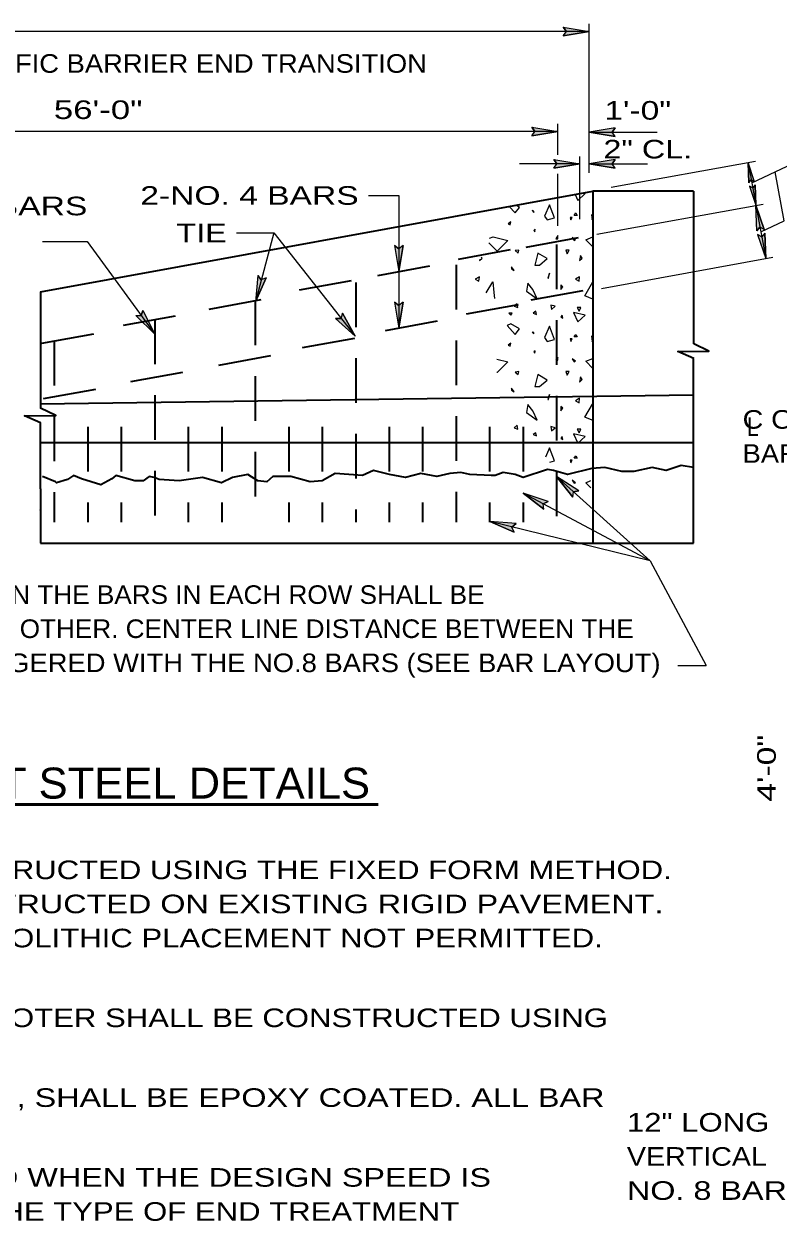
# Model space of a CAD drawing. Extents: x -11.7 to -4.5, y 8.6 to 18.8.
# Drawn here: x -8.704 to -6.272, y 11.081 to 14.943 of the extents above; entities that cross this region are included whole.
import ezdxf
from ezdxf.enums import TextEntityAlignment as Align

# ---------------------------------------------------------------- set-up
doc = ezdxf.new("R2010")
doc.units = 0
doc.header["$LTSCALE"] = 0.024
doc.linetypes.add('LONG_DASHED', pattern=[7.5, 6, -1.5])
for name, color, linetype, lineweight in [('1', 7, 'Continuous', 35), ('10', 7, 'Continuous', 13), ('12', 7, 'Continuous', 53), ('13', 7, 'Continuous', 53), ('6', 7, 'Continuous', 13)]:
    doc.layers.add(name, color=color, linetype=linetype, lineweight=lineweight)

msp = doc.modelspace()

# ---------------------------------------------------------------- hatches: boundary and pattern name
at = {"layer": '10'}
for points in [[(-6.8805, 14.919), (-6.9645, 14.905), (-6.954, 14.919), (-6.9645, 14.933)], [(-6.98233, 14.59633), (-7.06633, 14.58233), (-7.05583, 14.59633), (-7.06633, 14.61033)], [(-6.8805, 14.59433), (-6.7965, 14.58033), (-6.807, 14.59433), (-6.7965, 14.60833)], [(-6.91133, 14.49133), (-6.99533, 14.47733), (-6.98483, 14.49133), (-6.99533, 14.50533)], [(-6.8805, 14.49133), (-6.7965, 14.47733), (-6.807, 14.49133), (-6.7965, 14.50533)], [(-6.34717, 14.43383), (-6.36817, 14.4965), (-6.36583, 14.4305), (-6.358, 14.44017)], [(-6.34283, 14.35783), (-6.34533, 14.42367), (-6.35317, 14.414), (-6.364, 14.42017)], [(-6.34283, 14.35783), (-6.31667, 14.2795), (-6.33017, 14.2875), (-6.34017, 14.27533)], [(-6.3115, 14.186), (-6.31467, 14.2685), (-6.3245, 14.25617), (-6.338, 14.264)], [(-7.49467, 14.14417), (-7.48067, 14.22817), (-7.49467, 14.21767), (-7.50867, 14.22817)], [(-7.95733, 14.0465), (-7.92217, 14.12417), (-7.9385, 14.11767), (-7.94933, 14.13133)], [(-8.28217, 13.94267), (-8.343, 14.00233), (-8.3255, 14.00217), (-8.3205, 14.01883)], [(-7.49467, 13.96167), (-7.48067, 14.04567), (-7.49467, 14.03517), (-7.50867, 14.04567)], [(-7.636, 13.9355), (-7.67683, 14.01017), (-7.68133, 13.99317), (-7.699, 13.99283)], [(-6.98583, 13.483), (-6.93317, 13.416), (-6.9315, 13.4335), (-6.91417, 13.43683)], [(-7.09417, 13.42933), (-7.02667, 13.3775), (-7.02933, 13.39483), (-7.0135, 13.40217)], [(-7.2015, 13.33733), (-7.12317, 13.30383), (-7.13, 13.32), (-7.11667, 13.331)]]:
    msp.add_hatch(color=256, dxfattribs=at).paths.add_polyline_path(points)

# ---------------------------------------------------------------- linework, layer by layer
at = {"layer": '1'}
for p, q in [((-8.65083, 14.079), (-6.86867, 14.403)), ((-6.5445, 14.403), (-6.86867, 14.403)), ((-6.86867, 14.403), (-6.86867, 13.2685)), ((-7.08383, 14.223), (-6.91567, 14.25367)), ((-7.3025, 14.1845), (-7.1345, 14.21517)), ((-7.563, 14.1315), (-7.39483, 14.16217)), ((-7.81533, 14.085), (-7.64733, 14.1155)), ((-7.0685, 14.0525), (-6.9005, 14.083)), ((-8.10667, 14.02333), (-7.93867, 14.05383)), ((-7.27667, 14.0075), (-7.10867, 14.038)), ((-8.38283, 13.97117), (-8.21483, 14.00183)), ((-7.538, 13.95417), (-7.37, 13.98483)), ((-8.646, 13.91317), (-8.478, 13.94367)), ((-7.805, 13.89867), (-7.63683, 13.92917)), ((-8.07533, 13.84267), (-7.90717, 13.87317)), ((-8.35967, 13.789), (-8.1915, 13.81967)), ((-8.64067, 13.73417), (-8.4725, 13.76483)), ((-8.65167, 13.717), (-6.54483, 13.7465)), ((-8.65083, 13.59283), (-6.54483, 13.59283)), ((-8.65083, 13.2685), (-6.54483, 13.2685))]:
    msp.add_line(p, q, dxfattribs=at)
at = {"layer": '1', "linetype": 'LONG_DASHED'}
for p, q in [((-6.986, 14.23133), (-6.986, 13.33583)), ((-7.31, 14.16583), (-7.31, 13.33583)), ((-7.634, 14.109), (-7.634, 13.33583)), ((-7.958, 14.05033), (-7.958, 13.33583)), ((-8.28217, 13.9895), (-8.28217, 13.33583)), ((-8.60617, 13.92033), (-8.60617, 13.33583)), ((-8.49817, 13.64333), (-8.49817, 13.33583)), ((-8.39017, 13.64333), (-8.39017, 13.33583)), ((-8.17417, 13.64333), (-8.17417, 13.33583)), ((-8.06617, 13.64333), (-8.06617, 13.33583)), ((-7.85, 13.64333), (-7.85, 13.33583)), ((-7.742, 13.64333), (-7.742, 13.33583)), ((-7.526, 13.64333), (-7.526, 13.33583)), ((-7.418, 13.64333), (-7.418, 13.33583)), ((-7.202, 13.64333), (-7.202, 13.33583)), ((-7.094, 13.64333), (-7.094, 13.33583))]:
    msp.add_line(p, q, dxfattribs=at)
at = {"layer": '1'}
msp.add_lwpolyline([(-6.54483, 13.51167), (-6.58383, 13.51817), (-6.6325, 13.502), (-6.67783, 13.51167), (-6.73633, 13.49867), (-6.77533, 13.49867), (-6.8305, 13.51167), (-6.87267, 13.5085), (-6.9505, 13.489), (-6.996, 13.502), (-7.01533, 13.50517), (-7.09333, 13.47933), (-7.11917, 13.489), (-7.15817, 13.4955), (-7.18417, 13.48583), (-7.19717, 13.48583), (-7.26533, 13.489), (-7.2945, 13.4955), (-7.33017, 13.49233), (-7.37233, 13.4825), (-7.42433, 13.49233), (-7.473, 13.47933), (-7.52483, 13.489), (-7.57683, 13.502), (-7.6125, 13.48583), (-7.7, 13.49233), (-7.74233, 13.4695), (-7.78117, 13.46633), (-7.84283, 13.4825), (-7.90133, 13.4825), (-7.92083, 13.46633), (-7.95, 13.4695), (-7.98233, 13.489), (-8.03117, 13.47933), (-8.06683, 13.463), (-8.1285, 13.47933), (-8.203, 13.4695), (-8.268, 13.47283), (-8.28417, 13.47933), (-8.30033, 13.4825), (-8.31983, 13.4695), (-8.34583, 13.4695), (-8.4075, 13.48583), (-8.4205, 13.476), (-8.45617, 13.4565), (-8.51783, 13.476), (-8.54383, 13.48583), (-8.56333, 13.47283), (-8.599, 13.463), (-8.60217, 13.46633), (-8.64433, 13.4825)], dxfattribs=at)
at = {"layer": '10'}
for p, q in [((-6.8805, 14.919), (-9.01333, 14.919)), ((-6.9645, 14.933), (-6.8805, 14.919)), ((-6.9645, 14.933), (-6.954, 14.919)), ((-6.9645, 14.905), (-6.8805, 14.919)), ((-6.9645, 14.905), (-6.954, 14.919)), ((-6.8805, 14.463), (-6.8805, 14.943)), ((-7.06633, 14.61033), (-6.98233, 14.59633)), ((-7.06633, 14.61033), (-7.05583, 14.59633)), ((-6.98233, 14.52067), (-6.98233, 14.62033)), ((-6.7965, 14.60833), (-6.8805, 14.59433)), ((-6.7965, 14.60833), (-6.807, 14.59433)), ((-6.98233, 14.59633), (-8.962, 14.59633)), ((-7.06633, 14.58233), (-6.98233, 14.59633)), ((-7.06633, 14.58233), (-7.05583, 14.59633)), ((-6.8805, 14.59433), (-6.66117, 14.59433)), ((-6.7965, 14.58033), (-6.8805, 14.59433)), ((-6.7965, 14.58033), (-6.807, 14.59433)), ((-6.35617, 14.43083), (-6.13917, 14.5335)), ((-6.91133, 14.49133), (-7.10567, 14.49133)), ((-6.99533, 14.50533), (-6.91133, 14.49133)), ((-6.99533, 14.50533), (-6.98483, 14.49133)), ((-6.99533, 14.47733), (-6.91133, 14.49133)), ((-6.99533, 14.47733), (-6.98483, 14.49133)), ((-6.91133, 14.31367), (-6.91133, 14.51533)), ((-6.7965, 14.50533), (-6.8805, 14.49133)), ((-6.8805, 14.49133), (-6.69267, 14.49133)), ((-6.7965, 14.47733), (-6.8805, 14.49133)), ((-6.81, 14.41617), (-6.3445, 14.50083)), ((-6.7965, 14.50533), (-6.807, 14.49133)), ((-6.7965, 14.47733), (-6.807, 14.49133)), ((-6.36583, 14.4305), (-6.36817, 14.4965)), ((-6.34717, 14.43383), (-6.36817, 14.4965)), ((-6.98233, 14.2915), (-6.98233, 14.45967)), ((-6.36583, 14.4305), (-6.358, 14.44017)), ((-6.364, 14.42017), (-6.34283, 14.35783)), ((-6.364, 14.42017), (-6.35317, 14.414)), ((-6.34717, 14.43383), (-6.358, 14.44017)), ((-6.34533, 14.42367), (-6.35317, 14.414)), ((-6.34533, 14.42367), (-6.34283, 14.35783)), ((-7.59283, 14.38967), (-7.49467, 14.38967)), ((-6.85667, 14.26433), (-6.31933, 14.362)), ((-6.34017, 14.27533), (-6.34283, 14.35783)), ((-6.31667, 14.2795), (-6.34283, 14.35783)), ((-7.89833, 14.26883), (-7.95733, 14.0465)), ((-6.34017, 14.27533), (-6.33017, 14.2875)), ((-6.338, 14.264), (-6.3115, 14.186)), ((-6.338, 14.264), (-6.3245, 14.25617)), ((-6.31667, 14.2795), (-6.33017, 14.2875)), ((-6.31467, 14.2685), (-6.3245, 14.25617)), ((-6.31467, 14.2685), (-6.3115, 14.186)), ((-8.644, 14.24167), (-8.5005, 14.24167)), ((-8.5005, 14.24167), (-8.28217, 13.94267)), ((-7.50867, 14.22817), (-7.49467, 14.14417)), ((-7.50867, 14.22817), (-7.49467, 14.21767)), ((-7.48067, 14.22817), (-7.49467, 14.14417)), ((-7.48067, 14.22817), (-7.49467, 14.21767)), ((-6.84067, 14.08967), (-6.288, 14.19017)), ((-7.94933, 14.13133), (-7.95733, 14.0465)), ((-7.92217, 14.12417), (-7.95733, 14.0465)), ((-7.94933, 14.13133), (-7.9385, 14.11767)), ((-7.92217, 14.12417), (-7.9385, 14.11767)), ((-8.3205, 14.01883), (-8.3255, 14.00217)), ((-8.3205, 14.01883), (-8.28217, 13.94267)), ((-7.50867, 14.04567), (-7.49467, 13.96167)), ((-7.50867, 14.04567), (-7.49467, 14.03517)), ((-7.48067, 14.04567), (-7.49467, 13.96167)), ((-7.48067, 14.04567), (-7.49467, 14.03517)), ((-8.343, 14.00233), (-8.28217, 13.94267)), ((-8.343, 14.00233), (-8.3255, 14.00217)), ((-7.699, 13.99283), (-7.68133, 13.99317)), ((-7.699, 13.99283), (-7.636, 13.9355)), ((-7.67683, 14.01017), (-7.68133, 13.99317)), ((-7.67683, 14.01017), (-7.636, 13.9355)), ((-6.93317, 13.416), (-6.98583, 13.483)), ((-6.91417, 13.43683), (-6.98583, 13.483)), ((-6.68417, 13.21083), (-7.09417, 13.42933)), ((-7.02667, 13.3775), (-7.09417, 13.42933)), ((-7.0135, 13.40217), (-7.09417, 13.42933)), ((-7.0135, 13.40217), (-7.02933, 13.39483)), ((-6.93317, 13.416), (-6.9315, 13.4335)), ((-6.91417, 13.43683), (-6.9315, 13.4335)), ((-7.02667, 13.3775), (-7.02933, 13.39483)), ((-6.68417, 13.21083), (-7.2015, 13.33733)), ((-7.12317, 13.30383), (-7.2015, 13.33733)), ((-7.11667, 13.331), (-7.2015, 13.33733)), ((-7.11667, 13.331), (-7.13, 13.32)), ((-7.12317, 13.30383), (-7.13, 13.32)), ((-6.59517, 12.8735), (-6.504, 12.8735))]:
    msp.add_line(p, q, dxfattribs=at)
at = {"layer": '10', "lineweight": 35}
for p, q in [((-6.5445, 14.403), (-6.5445, 13.91083)), ((-8.65083, 14.079), (-8.65083, 13.70267)), ((-6.54483, 13.2685), (-6.54483, 13.86417)), ((-8.65083, 13.4435), (-8.65083, 13.65717)), ((-8.65083, 13.44283), (-8.65083, 13.2685)), ((-8.65083, 13.37467), (-8.65083, 13.37533))]:
    msp.add_line(p, q, dxfattribs=at)
at = {"layer": '10'}
for points in [[(-6.8805, 14.919), (-6.9645, 14.905), (-6.954, 14.919), (-6.9645, 14.933)], [(-6.98233, 14.59633), (-7.06633, 14.58233), (-7.05583, 14.59633), (-7.06633, 14.61033)], [(-6.8805, 14.59433), (-6.7965, 14.58033), (-6.807, 14.59433), (-6.7965, 14.60833)], [(-6.91133, 14.49133), (-6.99533, 14.47733), (-6.98483, 14.49133), (-6.99533, 14.50533)], [(-6.8805, 14.49133), (-6.7965, 14.47733), (-6.807, 14.49133), (-6.7965, 14.50533)], [(-6.34717, 14.43383), (-6.36817, 14.4965), (-6.36583, 14.4305), (-6.358, 14.44017)], [(-6.34283, 14.35783), (-6.34533, 14.42367), (-6.35317, 14.414), (-6.364, 14.42017)], [(-6.34283, 14.35783), (-6.31667, 14.2795), (-6.33017, 14.2875), (-6.34017, 14.27533)], [(-6.3115, 14.186), (-6.31467, 14.2685), (-6.3245, 14.25617), (-6.338, 14.264)], [(-7.49467, 14.14417), (-7.48067, 14.22817), (-7.49467, 14.21767), (-7.50867, 14.22817)], [(-7.95733, 14.0465), (-7.92217, 14.12417), (-7.9385, 14.11767), (-7.94933, 14.13133)], [(-8.28217, 13.94267), (-8.343, 14.00233), (-8.3255, 14.00217), (-8.3205, 14.01883)], [(-7.49467, 13.96167), (-7.48067, 14.04567), (-7.49467, 14.03517), (-7.50867, 14.04567)], [(-7.636, 13.9355), (-7.67683, 14.01017), (-7.68133, 13.99317), (-7.699, 13.99283)], [(-6.98583, 13.483), (-6.93317, 13.416), (-6.9315, 13.4335), (-6.91417, 13.43683)], [(-7.09417, 13.42933), (-7.02667, 13.3775), (-7.02933, 13.39483), (-7.0135, 13.40217)], [(-7.2015, 13.33733), (-7.12317, 13.30383), (-7.13, 13.32), (-7.11667, 13.331)]]:
    msp.add_lwpolyline(points, close=True, dxfattribs=at)
for points in [[(-6.36817, 14.4965), (-6.34283, 14.35783), (-6.3115, 14.186)], [(-6.32717, 14.27183), (-6.25233, 14.30733), (-6.28133, 14.46617)], [(-7.49467, 14.38967), (-7.49467, 14.14417), (-7.49467, 13.96367)], [(-8.01833, 14.26883), (-7.89833, 14.26883), (-7.636, 13.9355)], [(-6.98583, 13.483), (-6.68417, 13.21083), (-6.504, 12.8735)]]:
    msp.add_lwpolyline(points, dxfattribs=at)
at = {"layer": '10', "lineweight": 35}
for points in [[(-6.54367, 13.86417), (-6.59517, 13.88667), (-6.4945, 13.8875), (-6.54367, 13.91083)], [(-8.6505, 13.65633), (-8.702, 13.67883), (-8.60133, 13.67967), (-8.6505, 13.703)]]:
    msp.add_lwpolyline(points, dxfattribs=at)
at = {"layer": '12'}
msp.add_line((-9.947, 12.42533), (-7.561, 12.42533), dxfattribs=at)
at = {"layer": '6'}
for points in [[(-6.92633, 14.3925), (-6.91733, 14.37367), (-6.89333, 14.39567), (-6.9005, 14.39717)], [(-7.13867, 14.35383), (-7.1195, 14.33333), (-7.10517, 14.351), (-7.11683, 14.35783)], [(-6.86867, 14.32567), (-6.87317, 14.327), (-6.87083, 14.31067), (-6.86867, 14.31917)], [(-7.202, 14.2515), (-7.19, 14.2565), (-7.1435, 14.2445), (-7.178, 14.20983), (-7.205, 14.23683)], [(-6.86867, 14.2235), (-6.8915, 14.24633), (-6.86867, 14.25583)], [(-7.23417, 14.18317), (-7.23467, 14.17967), (-7.2265, 14.18783), (-7.22883, 14.191)], [(-7.213, 14.07533), (-7.192, 14.111), (-7.18817, 14.0765), (-7.18667, 14.057)], [(-6.86867, 14.05483), (-6.89533, 14.06633), (-6.86883, 14.111), (-6.86867, 14.10817)], [(-6.86867, 13.93383), (-6.87317, 13.93533), (-6.87083, 13.919), (-6.86867, 13.92733)], [(-7.17867, 13.86183), (-7.1435, 13.85267), (-7.178, 13.81817), (-7.17867, 13.81867)], [(-6.86867, 13.83183), (-6.8915, 13.85467), (-6.86867, 13.864)], [(-6.87167, 13.66433), (-6.89533, 13.67467), (-6.87067, 13.71617)], [(-7.00783, 13.5295), (-6.99233, 13.5335), (-7.00867, 13.57567), (-7.022, 13.54517)], [(-6.87567, 13.447), (-6.8915, 13.46283), (-6.87517, 13.46967)]]:
    msp.add_lwpolyline(points, dxfattribs=at)
for points in [[(-7.059, 14.339), (-7.06483, 14.341), (-7.059, 14.33517)], [(-7.01633, 14.31067), (-6.99233, 14.317), (-7.00867, 14.35917), (-7.0245, 14.32317)], [(-6.92367, 14.33333), (-6.91933, 14.32517), (-6.92933, 14.32517)], [(-7.14167, 14.29867), (-7.13583, 14.29483), (-7.1335, 14.305)], [(-6.94183, 14.31883), (-6.94, 14.31067), (-6.93567, 14.31883)], [(-7.05467, 14.2805), (-7.059, 14.27667), (-7.05667, 14.27233)], [(-6.98217, 14.26033), (-6.988, 14.25017), (-6.98217, 14.25017)], [(-6.92933, 14.2445), (-6.9255, 14.24633), (-6.93567, 14.2545)], [(-7.1195, 14.21183), (-7.1095, 14.20367), (-7.1075, 14.21367)], [(-6.95583, 14.21367), (-6.952, 14.20167), (-6.94567, 14.21367)], [(-7.04083, 14.16517), (-7.01633, 14.18583), (-7.0465, 14.20367), (-7.05667, 14.16517)], [(-6.90917, 14.196), (-6.91167, 14.17967), (-6.9035, 14.18783)], [(-7.1315, 14.1595), (-7.1315, 14.15317), (-7.12333, 14.1475)], [(-7.01433, 14.123), (-7.0125, 14.123), (-7.00867, 14.13933)], [(-7.24867, 14.11917), (-7.23667, 14.11283), (-7.23467, 14.12733)], [(-7.07917, 14.10667), (-7.083, 14.08067), (-7.049, 14.05633), (-7.06283, 14.0865)], [(-6.97217, 14.10083), (-6.97217, 14.0865), (-6.96583, 14.09467)], [(-6.9255, 14.11917), (-6.9135, 14.11283), (-6.91167, 14.12733)], [(-7.11333, 14.0405), (-7.12333, 14.03233), (-7.11133, 14.028)], [(-7.00433, 14.03617), (-7.00233, 14.02217), (-6.99033, 14.03233)], [(-6.91933, 14.028), (-6.9135, 14.016), (-6.90733, 14.028)], [(-7.13967, 14.01017), (-7.1335, 14.004), (-7.12967, 14.01017)], [(-7.061, 14.01017), (-7.05083, 14.00583), (-7.05283, 14.016)], [(-6.97217, 13.99767), (-6.96583, 13.99383), (-6.96783, 14.004)], [(-6.93183, 14.01217), (-6.91733, 13.98183), (-6.89333, 14.004)], [(-7.14583, 13.96983), (-7.1195, 13.9415), (-7.10517, 13.95933), (-7.1335, 13.97567)], [(-7.059, 13.94733), (-7.06483, 13.94917), (-7.059, 13.9435)], [(-7.01633, 13.919), (-6.99233, 13.92517), (-7.00867, 13.9675), (-7.0245, 13.9315)], [(-7.14167, 13.907), (-7.13583, 13.90317), (-7.1335, 13.91317)], [(-6.94183, 13.92717), (-6.94, 13.919), (-6.93567, 13.92717)], [(-6.92367, 13.9415), (-6.91933, 13.93333), (-6.92933, 13.93333)], [(-7.05467, 13.88867), (-7.059, 13.88483), (-7.05667, 13.8805)], [(-6.98217, 13.8685), (-6.988, 13.8585), (-6.98217, 13.8585)], [(-6.92933, 13.85267), (-6.9255, 13.85467), (-6.93567, 13.86283)], [(-7.1195, 13.82), (-7.1095, 13.81183), (-7.1075, 13.822)], [(-7.04083, 13.7735), (-7.01633, 13.79417), (-7.0465, 13.81183), (-7.05667, 13.7735)], [(-6.95583, 13.822), (-6.952, 13.81), (-6.94567, 13.822)], [(-6.90917, 13.80417), (-6.91167, 13.78783), (-6.9035, 13.796)], [(-7.1315, 13.76767), (-7.1315, 13.7615), (-7.12333, 13.75567)], [(-7.07917, 13.715), (-7.083, 13.689), (-7.049, 13.6645), (-7.06283, 13.69483)], [(-7.01433, 13.73133), (-7.0125, 13.73133), (-7.00867, 13.7475)], [(-6.9255, 13.72733), (-6.9135, 13.72117), (-6.91167, 13.7355)], [(-6.97217, 13.70917), (-6.97217, 13.69483), (-6.96583, 13.703)], [(-7.11333, 13.64867), (-7.12333, 13.6405), (-7.11133, 13.63617)], [(-7.00433, 13.64433), (-7.00233, 13.6305), (-6.99033, 13.6405)], [(-6.91933, 13.63617), (-6.9135, 13.62417), (-6.90733, 13.63617)], [(-7.061, 13.6185), (-7.05083, 13.61417), (-7.05283, 13.62417)], [(-6.97217, 13.606), (-6.96583, 13.60217), (-6.96783, 13.61217)], [(-6.93183, 13.62033), (-6.91733, 13.59017), (-6.89333, 13.61217)], [(-6.94183, 13.53533), (-6.94, 13.52717), (-6.93567, 13.53533)], [(-6.92367, 13.54983), (-6.91933, 13.54167), (-6.92933, 13.54167)], [(-6.92933, 13.461), (-6.9255, 13.46283), (-6.93567, 13.471)]]:
    msp.add_lwpolyline(points, close=True, dxfattribs=at)

# ---------------------------------------------------------------- texts
at = {"layer": '12'}
for s, height, width, p in [('PAYMENT PER EACH FOR CONCRETE MEDIAN TRAFFIC BARRIER END TRANSITION', 0.06, 1.1, (-9.19642, 14.78542)), ('56\'-0"', 0.06001, 1.4, (-8.46458, 14.63625)), ('1\'-0"', 0.06001, 1.35, (-6.72417, 14.63425)), ('2" CL.', 0.06001, 1.3, (-6.69179, 14.50908)), ('REINFORCEMENT STEEL DETAILS', 0.1, 1.05, (-8.754, 12.44392))]:
    msp.add_text(s, height=height, dxfattribs=dict(at, width=width)).set_placement(p, align=Align.CENTER)
for s, width, p in [('2-NO. 4 BARS', 1.35, (-7.62433, 14.35958)), ('TIE', 1.3, (-8.04983, 14.23875))]:
    msp.add_text(s, height=0.06001, dxfattribs=dict(at, width=width)).set_placement(p, align=Align.RIGHT)
for s, width, p in [('15 VERTICAL NO. 4 BARS', 1.35, (-9.818, 14.32567)), ('C OF', 1.15, (-6.386, 13.63717)), ('L', 0.85, (-6.37183, 13.61383)), ('BARRIER', 1.1, (-6.38608, 13.52717)), ('TWO ROWS OF 12 LONG VERTICAL NO. 8 BARS. DISTANCE BETWEEN THE BARS IN EACH ROW SHALL BE', 1.05, (-11.5305, 13.072)), ('4\'-0" C/C. ONE ROW OF THE BARS SHALL BE STAGGERED WITH THE OTHER. CENTER LINE DISTANCE BETWEEN THE', 1.05, (-11.5305, 12.962)), ('BARS SHALL BE 2\'-0". THE VERTICAL NO.4 BARS SHALL BE STAGGERED WITH THE NO.8 BARS (SEE BAR LAYOUT)', 1.1, (-11.5305, 12.852)), ('12" LONG', 1.25, (-6.75908, 11.36958)), ('VERTICAL', 1.15, (-6.75908, 11.2595)), ('NO. 8 BARS', 1.3, (-6.75908, 11.1495))]:
    msp.add_text(s, height=0.06001, dxfattribs=dict(at, width=width)).set_placement(p)
at = {"layer": '12', "width": 1.35}
msp.add_text('4\'-0"', height=0.06001, rotation=90, dxfattribs=at).set_placement((-6.279, 12.54208), align=Align.CENTER)
at = {"layer": '13'}
for s, width, p in [('1. THE TRAFFIC BARRIER END TRANSITION SHALL BE CONSTRUCTED USING THE FIXED FORM METHOD.', 1.25, (-11.74175, 12.18408)), ('   NO FOOTER IS REQUIRED WHEN THE BARRIER IS CONSTRUCTED ON EXISTING RIGID PAVEMENT.', 1.3, (-11.74175, 12.07408)), ('   BARRIER AND FOOTER SHALL BE CAST SEPARATELY. MONOLITHIC PLACEMENT NOT PERMITTED.', 1.25, (-11.74175, 11.96408)), ('2. THE TRAFFIC BARRIER END TRANSITION AND BARRIER FOOTER SHALL BE CONSTRUCTED USING', 1.25, (-11.74175, 11.70675)), ('3. ALL REINFORCEMENT BARS, INCLUDING ENDS AND TIES, SHALL BE EPOXY COATED. ALL BAR', 1.3, (-11.74183, 11.44933)), ('4. THIS TRAFFIC BARRIER END TRANSITION IS PROHIBITED WHEN THE DESIGN SPEED IS', 1.3, (-11.74183, 11.19192)), ('   45 MPH OR GREATER. THE ENGINEER MUST DETERMINE THE TYPE OF END TREATMENT', 1.25, (-11.74183, 11.08192))]:
    msp.add_text(s, height=0.06001, dxfattribs=dict(at, width=width)).set_placement(p)

doc.saveas('drawing.dxf')
